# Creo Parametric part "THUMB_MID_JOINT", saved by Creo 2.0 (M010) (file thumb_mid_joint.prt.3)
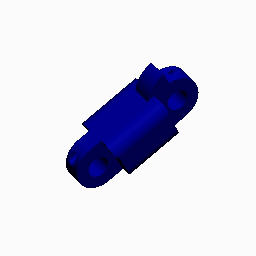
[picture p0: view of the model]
Units: Inch lbm Second (Pro/E Default); INCH, POUND, SECS

Created from: INLBS_PART_SOLID.PRT

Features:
  1. datum plane "RIGHT"
  2. datum plane "TOP"
  3. datum plane "FRONT"
  4. coordinate system
  5. sketch "Sketch 1"
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
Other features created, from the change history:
  extrusion "Extrude 1"
  sketch "Sketch 2"
  extrusion "Extrude 2"
  round "Round 1"
  round "Round 2"
  sketch "Sketch 3"
  extruded cut "Extrude 3"
  mirror "Mirror 1" (2 times)
  sketch "Sketch 3 (2)"
  extruded cut "Extrude 4"
  mirror "Mirror 2"
  extruded cut "Extrude 5"
  mirror "Mirror 3"
  extruded cut "Extrude 6"
  sketch "Sketch 4"
  extrusion "Extrude 7"
  sketch "Sketch 5"
  extruded cut "Extrude 8"
  sketch "Sketch 6"
  extruded cut "Extrude 9"
  sketch "Sketch 7"
  extrusion "Extrude 10"

Surfaces: 21 plane, 21 cylinder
